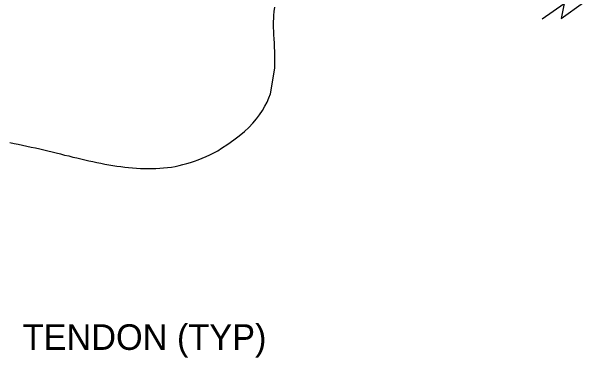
# Model space of a CAD drawing. Extents: x 638850 to 644908, y 297188 to 298900.
# Drawn here: x 639021.7 to 639088.7, y 297716.1 to 297756.7 of the extents above; entities that cross this region are included whole.
import ezdxf

# ---------------------------------------------------------------- set-up
doc = ezdxf.new("R2010")
doc.units = 0
doc.layers.add('1', color=7, linetype='Continuous')
doc.layers.add('2', color=7, linetype='Continuous')

msp = doc.modelspace()

# ---------------------------------------------------------------- linework, layer by layer
at = {"layer": '1'}
msp.add_lwpolyline([(639083.828, 297755.813), (639086.388, 297757.614), (639086.031, 297755.828), (639088.656, 297757.704)], dxfattribs=at)
at = {"layer": '2'}
for p, q in [((639052.461, 297756.67), (639052.539, 297757.181)), ((639052.416, 297756.178), (639052.461, 297756.67)), ((639052.382, 297755.158), (639052.416, 297756.178)), ((639052.382, 297754.756), (639052.382, 297755.158)), ((639052.382, 297755.158), (639052.382, 297755.158)), ((639052.398, 297754.339), (639052.382, 297754.756)), ((639052.416, 297753.939), (639052.398, 297754.339)), ((639052.445, 297753.444), (639052.416, 297753.939)), ((639052.476, 297752.967), (639052.445, 297753.444)), ((639052.49, 297752.472), (639052.476, 297752.967)), ((639052.524, 297751.993), (639052.49, 297752.472)), ((639052.539, 297751.5), (639052.524, 297751.993)), ((639052.539, 297751.005), (639052.539, 297751.5)), ((639052.539, 297750.51), (639052.539, 297751.005)), ((639052.524, 297750.015), (639052.539, 297750.51)), ((639052.002, 297747.021), (639052.524, 297750.015))]:
    msp.add_line(p, q, dxfattribs=at)
for points in [[(639042.671, 297738.958), (639043.119, 297739.114), (639043.564, 297739.282), (639044.028, 297739.451), (639044.478, 297739.654), (639044.925, 297739.87), (639045.373, 297740.101), (639045.834, 297740.347), (639046.282, 297740.628), (639046.282, 297740.628), (639047.038, 297741.123), (639047.736, 297741.6), (639048.368, 297742.095), (639048.955, 297742.588), (639049.479, 297743.083), (639049.945, 297743.575), (639050.377, 297744.07), (639050.746, 297744.565), (639051.086, 297745.058), (639051.365, 297745.553), (639051.626, 297746.046), (639051.828, 297746.541), (639052.002, 297747.021)], [(639021.496, 297741.289), (639022.005, 297741.197), (639022.5, 297741.105), (639023.008, 297740.997), (639023.503, 297740.887), (639024.014, 297740.779), (639024.507, 297740.673), (639025.002, 297740.549), (639025.479, 297740.441), (639025.974, 297740.317), (639026.471, 297740.196), (639026.948, 297740.086), (639027.443, 297739.962), (639027.92, 297739.84), (639028.399, 297739.732), (639028.876, 297739.606), (639029.358, 297739.498), (639029.819, 297739.375), (639030.298, 297739.267), (639030.762, 297739.159), (639031.241, 297739.066), (639031.702, 297738.958), (639032.168, 297738.868), (639032.645, 297738.774), (639033.111, 297738.695), (639033.572, 297738.619), (639034.035, 297738.54), (639034.501, 297738.479), (639034.949, 297738.418), (639035.41, 297738.373), (639035.874, 297738.324), (639036.324, 297738.295), (639036.785, 297738.263), (639037.233, 297738.25), (639037.696, 297738.25), (639038.146, 297738.25), (639038.607, 297738.263), (639039.055, 297738.295), (639039.503, 297738.324), (639039.969, 297738.373), (639040.416, 297738.432), (639040.862, 297738.511), (639041.31, 297738.603), (639041.773, 297738.711), (639042.223, 297738.835), (639042.671, 297738.958)]]:
    msp.add_lwpolyline(points, dxfattribs=at)

# ---------------------------------------------------------------- texts
at = {"layer": '1'}
msp.add_text('TENDON (TYP)', height=3, dxfattribs=at).set_placement((639023.015, 297716.998))

doc.saveas('drawing.dxf')
